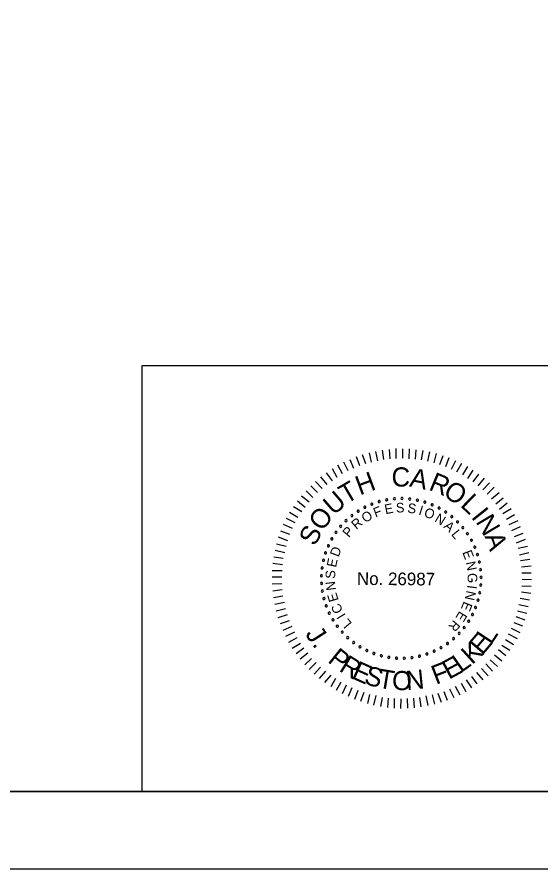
# Model space of a CAD drawing. Extents: x -125.5 to -89.4, y -5.1 to 16.9.
# Drawn here: x -103.71 to -100.32, y -5.07 to 0.43 of the extents above; entities that cross this region are included whole.
import ezdxf

# ---------------------------------------------------------------- set-up
doc = ezdxf.new("R2010")
doc.units = 0
for name, color, linetype in [('BR_BORDER LINES', 7, 'Continuous'), ('BR_TABLE LINES', 7, 'Continuous'), ('BR_TEXT', 7, 'Continuous'), ('Level 31', 7, 'Continuous')]:
    doc.layers.add(name, color=color, linetype=linetype)

msp = doc.modelspace()

# ---------------------------------------------------------------- linework, layer by layer
at = {"layer": 'BR_BORDER LINES'}
for p, q in [((-102.8989, -1.8161), (-97.5337, -1.8161)), ((-102.8989, -4.5661), (-102.8989, -1.8161)), ((-123.6994, -4.5662), (-90.0334, -4.5662))]:
    msp.add_line(p, q, dxfattribs=at)
at = {"layer": 'BR_TABLE LINES'}
msp.add_lwpolyline([(-123.6994, 16.4338), (-90.0334, 16.4338), (-90.0334, -4.5662), (-123.6994, -4.5662)], close=True, dxfattribs=at)
at = {"layer": 'BR_TEXT'}
for p, q in [((-101.3372, -2.423), (-101.3461, -2.362)), ((-101.2977, -2.419), (-101.3015, -2.3581)), ((-101.2582, -2.4168), (-101.2576, -2.3524)), ((-101.2161, -2.4146), (-101.2156, -2.3528)), ((-101.1741, -2.4175), (-101.1718, -2.3531)), ((-101.1338, -2.4204), (-101.129, -2.3595)), ((-101.0952, -2.425), (-101.0844, -2.3642)), ((-101.4937, -2.4629), (-101.5147, -2.4044)), ((-101.4541, -2.4504), (-101.476, -2.3927)), ((-101.418, -2.4404), (-101.4312, -2.3793)), ((-101.3767, -2.4304), (-101.3908, -2.3711)), ((-101.0549, -2.4331), (-101.0407, -2.374)), ((-101.0138, -2.4437), (-100.9979, -2.3829)), ((-100.977, -2.4543), (-100.9551, -2.397)), ((-100.9376, -2.4675), (-100.9157, -2.4093)), ((-101.604, -2.5144), (-101.6344, -2.46)), ((-101.5695, -2.4966), (-101.5957, -2.4406)), ((-101.5325, -2.4798), (-101.556, -2.4238)), ((-100.9017, -2.485), (-100.8738, -2.4294)), ((-100.8658, -2.5024), (-100.8345, -2.4469)), ((-100.8282, -2.5208), (-100.796, -2.467)), ((-101.6704, -2.5593), (-101.7095, -2.5083)), ((-101.6394, -2.5381), (-101.6698, -2.4838)), ((-100.795, -2.5451), (-100.761, -2.4913)), ((-100.7617, -2.5668), (-100.7252, -2.5165)), ((-101.7369, -2.6094), (-101.7786, -2.5644)), ((-101.7041, -2.5847), (-101.744, -2.5346)), ((-100.7293, -2.5928), (-100.6886, -2.5434)), ((-100.6977, -2.618), (-100.6545, -2.5737)), ((-101.7958, -2.6673), (-101.8392, -2.6248)), ((-101.7663, -2.6366), (-101.8106, -2.5925)), ((-100.6697, -2.6456), (-100.6264, -2.6022)), ((-100.6416, -2.6768), (-100.594, -2.6351)), ((-101.8469, -2.732), (-101.8964, -2.6922)), ((-101.8209, -2.6988), (-101.8704, -2.6598)), ((-100.6144, -2.7088), (-100.5677, -2.6705)), ((-101.8686, -2.761), (-101.9224, -2.728)), ((-100.5906, -2.7424), (-100.5414, -2.7033)), ((-100.5686, -2.7718), (-100.516, -2.7396)), ((-101.9104, -2.8319), (-101.9668, -2.804)), ((-101.893, -2.7977), (-101.9467, -2.7656)), ((-100.5466, -2.8089), (-100.4931, -2.7776)), ((-101.9279, -2.8687), (-101.9852, -2.8433)), ((-100.5288, -2.8433), (-100.4711, -2.8164)), ((-100.5111, -2.8804), (-100.4543, -2.856)), ((-101.9454, -2.9072), (-102.0035, -2.8852)), ((-100.4943, -2.9192), (-100.4374, -2.8982)), ((-101.97, -2.9833), (-102.0308, -2.9682)), ((-101.9577, -2.9474), (-102.0193, -2.9246)), ((-100.4809, -2.9596), (-100.4232, -2.9378)), ((-101.9772, -3.0253), (-102.0397, -3.0094)), ((-100.4708, -2.9957), (-100.4107, -2.9816)), ((-100.4626, -3.0378), (-100.4024, -3.0229)), ((-101.9878, -3.0613), (-102.0487, -3.0531)), ((-100.4543, -3.074), (-100.3951, -3.0667)), ((-101.9925, -3.1024), (-102.0542, -3.0951)), ((-100.4478, -3.1152), (-100.3868, -3.1088)), ((-101.9974, -3.183), (-102.06, -3.1825)), ((-101.9954, -3.1419), (-102.0597, -3.1414)), ((-100.4464, -3.1547), (-100.3863, -3.1552)), ((-101.9961, -3.226), (-102.0604, -3.2272)), ((-100.4471, -3.2388), (-100.3871, -3.241)), ((-100.4442, -3.1959), (-100.3833, -3.1964)), ((-101.9938, -3.2646), (-102.0556, -3.2718)), ((-100.4492, -3.2774), (-100.3883, -3.2856)), ((-101.9898, -3.3058), (-102.0509, -3.3148)), ((-101.9799, -3.3454), (-102.0426, -3.3586)), ((-100.4564, -3.3185), (-100.3972, -3.3284)), ((-101.9733, -3.3875), (-102.0344, -3.4016)), ((-100.4742, -3.3999), (-100.4143, -3.415)), ((-100.4653, -3.3579), (-100.4053, -3.3721)), ((-101.9616, -3.4245), (-102.0236, -3.4454)), ((-101.95, -3.4632), (-102.0085, -3.4842)), ((-100.4848, -3.4367), (-100.4275, -3.4586)), ((-101.9331, -3.5003), (-101.9908, -3.5272)), ((-100.5163, -3.512), (-100.4599, -3.5399)), ((-100.4989, -3.4752), (-100.4424, -3.4971)), ((-101.9162, -3.5364), (-101.9731, -3.566)), ((-101.8994, -3.5735), (-101.9537, -3.6048)), ((-100.5346, -3.5479), (-100.4774, -3.5784)), ((-101.8756, -3.6106), (-101.93, -3.6419)), ((-100.5756, -3.6213), (-100.5235, -3.6535)), ((-100.553, -3.5846), (-100.5, -3.6168)), ((-101.8544, -3.6399), (-101.9045, -3.6764)), ((-101.829, -3.6736), (-101.8791, -3.7127)), ((-100.6224, -3.6836), (-100.5764, -3.7234)), ((-100.5981, -3.6503), (-100.5495, -3.6876)), ((-101.8043, -3.7073), (-101.8485, -3.7481)), ((-101.7754, -3.7333), (-101.8204, -3.7784)), ((-100.6502, -3.7168), (-100.6033, -3.7584)), ((-101.7465, -3.7636), (-101.7889, -3.8095)), ((-101.714, -3.7895), (-101.7548, -3.8364)), ((-100.7073, -3.7721), (-100.6648, -3.8188)), ((-100.6787, -3.7423), (-100.6362, -3.7882)), ((-101.6808, -3.8156), (-101.7207, -3.8633)), ((-101.6501, -3.8373), (-101.6814, -3.8894)), ((-100.8057, -3.8443), (-100.7727, -3.8969)), ((-100.772, -3.8231), (-100.7364, -3.8714)), ((-100.7392, -3.7976), (-100.6993, -3.8452)), ((-101.6151, -3.8599), (-101.6464, -3.9137)), ((-101.5809, -3.8799), (-101.608, -3.9355)), ((-101.5442, -3.8974), (-101.5687, -3.953)), ((-100.9135, -3.9026), (-100.8865, -3.9586)), ((-100.8773, -3.8857), (-100.8468, -3.9418)), ((-100.8393, -3.8663), (-100.808, -3.9206)), ((-101.5057, -3.9149), (-101.5276, -3.9713)), ((-101.4663, -3.9272), (-101.4891, -3.9854)), ((-101.4304, -3.9395), (-101.4446, -3.9986)), ((-101.3892, -3.9467), (-101.4044, -4.0084)), ((-101.3499, -3.9582), (-101.3598, -4.0165)), ((-101.0675, -3.9494), (-101.0542, -4.0113)), ((-101.0262, -3.9429), (-101.0112, -4.0022)), ((-100.9892, -3.9311), (-100.9682, -3.9897)), ((-100.9496, -3.9194), (-100.9286, -3.9763)), ((-101.3104, -3.9628), (-101.3152, -4.0246)), ((-101.271, -3.9657), (-101.2715, -4.0275)), ((-101.229, -3.9686), (-101.2295, -4.0296)), ((-101.1869, -3.9664), (-101.1857, -4.0282)), ((-101.1466, -3.9642), (-101.1428, -4.026)), ((-101.1079, -3.9602), (-101.098, -4.0186))]:
    msp.add_line(p, q, dxfattribs=at)
for centre, start, end in [((-101.3681, -2.6945), 16.1422, 196.1422), ((-101.3681, -2.6945), 196.1422, 16.1422), ((-101.3196, -2.6831), 10.6038, 190.6038), ((-101.3196, -2.6831), 190.6038, 10.6038), ((-101.2702, -2.6764), 5.0653, 185.0653), ((-101.2702, -2.6764), 185.0653, 5.0653), ((-101.2204, -2.6745), 359.5268, 179.5268), ((-101.2204, -2.6745), 179.5268, 359.5268), ((-101.1707, -2.6774), 173.9884, 353.9884), ((-101.1707, -2.6774), 353.9884, 173.9884), ((-101.1214, -2.6851), 168.4499, 348.4499), ((-101.1214, -2.6851), 348.4499, 168.4499), ((-101.0732, -2.6976), 342.9114, 162.9114), ((-101.5039, -2.7559), 32.7576, 212.7576), ((-101.4607, -2.7311), 27.2191, 207.2191), ((-101.4607, -2.7311), 207.2191, 27.2191), ((-101.4153, -2.7106), 21.6807, 201.6807), ((-101.4153, -2.7106), 201.6807, 21.6807), ((-101.0732, -2.6976), 162.9114, 342.9114), ((-101.0263, -2.7146), 157.373, 337.373), ((-101.0263, -2.7146), 337.373, 157.373), ((-100.9814, -2.736), 151.8345, 331.8345), ((-100.9814, -2.736), 331.8345, 151.8345), ((-101.5445, -2.7848), 38.2961, 218.2961), ((-101.5445, -2.7848), 218.2961, 38.2961), ((-101.5039, -2.7559), 212.7576, 32.7576), ((-100.9387, -2.7617), 146.2961, 326.2961), ((-100.9387, -2.7617), 326.2961, 146.2961), ((-100.8987, -2.7914), 140.7576, 320.7576), ((-100.8987, -2.7914), 320.7576, 140.7576), ((-101.6164, -2.8536), 49.373, 229.373), ((-101.6164, -2.8536), 229.373, 49.373), ((-101.5821, -2.8175), 43.8345, 223.8345), ((-101.5821, -2.8175), 223.8345, 43.8345), ((-100.8617, -2.8249), 135.2191, 315.2191), ((-100.8617, -2.8249), 315.2191, 135.2191), ((-100.8282, -2.8617), 129.6807, 309.6807), ((-100.8282, -2.8617), 309.6807, 129.6807), ((-101.6471, -2.8929), 54.9114, 234.9114), ((-101.6471, -2.8929), 234.9114, 54.9114), ((-100.7983, -2.9016), 124.1422, 304.1422), ((-100.7983, -2.9016), 304.1422, 124.1422), ((-101.6738, -2.935), 60.4499, 240.4499), ((-101.6738, -2.935), 240.4499, 60.4499), ((-100.7724, -2.9442), 118.6038, 298.6038), ((-100.7724, -2.9442), 298.6038, 118.6038), ((-101.7145, -3.0258), 71.5268, 251.5268), ((-101.7145, -3.0258), 251.5268, 71.5268), ((-101.6964, -2.9794), 65.9884, 245.9884), ((-101.6964, -2.9794), 245.9884, 65.9884), ((-100.7508, -2.9891), 113.0653, 293.0653), ((-100.7508, -2.9891), 293.0653, 113.0653), ((-101.7281, -3.0738), 77.0653, 257.0653), ((-101.7281, -3.0738), 257.0653, 77.0653), ((-100.7336, -3.0359), 107.5268, 287.5268), ((-100.7336, -3.0359), 287.5268, 107.5268), ((-100.721, -3.0841), 101.9884, 281.9884), ((-100.721, -3.0841), 281.9884, 101.9884), ((-101.737, -3.1228), 82.6038, 262.6038), ((-101.737, -3.1228), 262.6038, 82.6038), ((-100.7131, -3.1333), 96.4499, 276.4499), ((-100.7131, -3.1333), 276.4499, 96.4499), ((-101.7411, -3.1724), 88.1422, 268.1422), ((-101.7411, -3.1724), 268.1422, 88.1422), ((-100.71, -3.183), 90.9114, 270.9114), ((-100.71, -3.183), 270.9114, 90.9114), ((-101.7404, -3.2223), 93.6807, 273.6807), ((-101.7404, -3.2223), 273.6807, 93.6807), ((-100.7118, -3.2328), 85.373, 265.373), ((-100.7118, -3.2328), 265.373, 85.373), ((-101.7349, -3.2718), 99.2191, 279.2191), ((-101.7349, -3.2718), 279.2191, 99.2191), ((-100.7183, -3.2822), 79.8345, 259.8345), ((-100.7183, -3.2822), 259.8345, 79.8345), ((-101.7246, -3.3206), 104.7576, 284.7576), ((-101.7246, -3.3206), 284.7576, 104.7576), ((-100.7295, -3.3308), 74.2961, 254.2961), ((-100.7295, -3.3308), 254.2961, 74.2961), ((-101.7097, -3.3681), 110.2961, 290.2961), ((-101.7097, -3.3681), 290.2961, 110.2961), ((-101.6903, -3.414), 115.8345, 295.8345), ((-101.6903, -3.414), 295.8345, 115.8345), ((-100.7454, -3.378), 68.7576, 248.7576), ((-100.7454, -3.378), 248.7576, 68.7576), ((-101.6665, -3.4578), 121.373, 301.373), ((-101.6665, -3.4578), 301.373, 121.373), ((-100.7904, -3.4668), 57.6807, 237.6807), ((-100.7904, -3.4668), 237.6807, 57.6807), ((-100.7658, -3.4235), 63.2191, 243.2191), ((-100.7658, -3.4235), 243.2191, 63.2191), ((-101.6386, -3.4991), 126.9114, 306.9114), ((-101.6386, -3.4991), 306.9114, 126.9114), ((-100.8192, -3.5075), 52.1422, 232.1422), ((-100.8192, -3.5075), 232.1422, 52.1422), ((-101.6069, -3.5375), 132.4499, 312.4499), ((-101.6069, -3.5375), 312.4499, 132.4499), ((-101.5716, -3.5727), 137.9884, 317.9884), ((-101.5716, -3.5727), 317.9884, 137.9884), ((-100.8877, -3.5797), 41.0653, 221.0653), ((-100.8517, -3.5452), 46.6038, 226.6038), ((-100.8517, -3.5452), 226.6038, 46.6038), ((-101.5331, -3.6043), 143.5268, 323.5268), ((-101.5331, -3.6043), 323.5268, 143.5268), ((-101.4917, -3.632), 149.0653, 329.0653), ((-101.4917, -3.632), 329.0653, 149.0653), ((-100.9269, -3.6105), 35.5268, 215.5268), ((-100.9269, -3.6105), 215.5268, 35.5268), ((-100.8877, -3.5797), 221.0653, 41.0653), ((-101.4478, -3.6556), 154.6038, 334.6038), ((-101.4478, -3.6556), 334.6038, 154.6038), ((-101.4018, -3.6749), 160.1422, 340.1422), ((-101.4018, -3.6749), 340.1422, 160.1422), ((-101.3542, -3.6896), 345.6807, 165.6807), ((-101.0595, -3.6784), 18.9114, 198.9114), ((-101.0595, -3.6784), 198.9114, 18.9114), ((-101.0132, -3.6601), 24.4499, 204.4499), ((-101.0132, -3.6601), 204.4499, 24.4499), ((-100.9688, -3.6374), 29.9884, 209.9884), ((-100.9688, -3.6374), 209.9884, 29.9884), ((-101.3542, -3.6896), 165.6807, 345.6807), ((-101.3054, -3.6997), 351.2191, 171.2191), ((-101.3054, -3.6997), 171.2191, 351.2191), ((-101.2559, -3.705), 356.7576, 176.7576), ((-101.2559, -3.705), 176.7576, 356.7576), ((-101.2061, -3.7055), 2.2961, 182.2961), ((-101.2061, -3.7055), 182.2961, 2.2961), ((-101.1564, -3.7012), 7.8345, 187.8345), ((-101.1564, -3.7012), 187.8345, 7.8345), ((-101.1074, -3.6921), 13.373, 193.373), ((-101.1074, -3.6921), 193.373, 13.373)]:
    msp.add_arc(centre, 0.00701, start, end, dxfattribs=at)
at = {"layer": 'Level 31'}
msp.add_lwpolyline([(-125.5328, -5.0661), (-89.5328, -5.0661), (-89.5328, 16.9339), (-125.5328, 16.9339)], close=True, dxfattribs=at)

# ---------------------------------------------------------------- texts
at = {"layer": 'BR_TEXT'}
for s, height, rotation, p in [('C', 0.1241, 359.5482, (-101.2889, -2.5969)), ('H', 0.1241, 20.3637, (-101.4933, -2.6552)), ('A', 0.1241, 348.1981, (-101.1775, -2.5961)), ('R', 0.1241, 337.4344, (-101.0542, -2.616)), ('T', 0.1241, 30.4992, (-101.5812, -2.7128)), ('O', 0.1239, 326.5869, (-100.962, -2.6528)), ('U', 0.1241, 40.8022, (-101.6624, -2.7875)), ('L', 0.1241, 315.9488, (-100.8494, -2.7205)), ('O', 0.1241, 52.0267, (-101.7369, -2.8914)), ('F', 0.0622, 20.6127, (-101.392, -2.7981)), ('E', 0.0622, 11.4103, (-101.3269, -2.7764)), ('S', 0.0622, 2.208, (-101.2591, -2.7654)), ('S', 0.0622, 352.6608, (-101.1878, -2.7657)), ('I', 0.0622, 343.1136, (-101.1175, -2.7777)), ('O', 0.0622, 338.4392, (-101.0841, -2.7878)), ('I', 0.1241, 308.6613, (-100.778, -2.7948)), ('R', 0.0622, 40.3949, (-101.5156, -2.878)), ('O', 0.0622, 30.8477, (-101.4594, -2.8341)), ('N', 0.0622, 328.2042, (-101.0145, -2.8192)), ('N', 0.1241, 300.7037, (-100.7474, -2.8242)), ('S', 0.1239, 63.2511, (-101.7823, -2.9871)), ('P', 0.0622, 49.9421, (-101.5636, -2.9306)), ('A', 0.0622, 318.657, (-100.9555, -2.8592)), ('L', 0.0622, 309.4546, (-100.9057, -2.9066)), ('A', 0.1241, 289.4792, (-100.6882, -2.9172)), ('D', 0.0622, 69.0364, (-101.6306, -3.0559)), ('E', 0.0622, 291.049, (-100.8319, -3.0219)), ('E', 0.0622, 78.2388, (-101.6472, -3.1226)), ('N', 0.0622, 281.8466, (-100.8097, -3.0869)), ('S', 0.0622, 87.786, (-101.6529, -3.1936)), ('No. 26987', 0.08175, 359.5268, (-101.5118, -3.232)), ('G', 0.0622, 272.2995, (-100.7979, -3.1572)), ('N', 0.0622, 97.3332, (-101.6467, -3.2646)), ('I', 0.0622, 262.4084, (-100.7983, -3.231)), ('E', 0.0622, 106.5355, (-101.6297, -3.3312)), ('N', 0.0622, 257.7339, (-100.8028, -3.2656)), ('C', 0.0622, 116.4266, (-101.5998, -3.3987)), ('E', 0.0622, 248.1867, (-100.8209, -3.3346)), ('E', 0.0622, 238.9844, (-100.8488, -3.3973)), ('I', 0.0622, 121.1011, (-101.5818, -3.4285)), ('L', 0.0622, 129.9595, (-101.5411, -3.4807)), ('R', 0.0622, 229.782, (-100.8865, -3.4548)), ('J', 0.1236, 302.9559, (-101.849, -3.5492)), ('E', 0.1236, 49.3639, (-100.703, -3.6911)), ('L', 0.1236, 56.4247, (-100.6455, -3.6233)), ('.', 0.1236, 309.3974, (-101.8049, -3.6172)), ('K', 0.1236, 42.3031, (-100.7683, -3.7512)), ('P', 0.1236, 321.1035, (-101.7065, -3.7264)), ('R', 0.1236, 328.5359, (-101.6332, -3.7844)), ('E', 0.1236, 335.9684, (-101.5531, -3.8325)), ('F', 0.1236, 21.1206, (-101.0013, -3.8776)), ('E', 0.1236, 28.1814, (-100.9186, -3.8452)), ('L', 0.1236, 35.2422, (-100.8406, -3.8028)), ('S', 0.1236, 343.0292, (-101.4718, -3.8682)), ('T', 0.1236, 350.4617, (-101.3821, -3.8947)), ('O', 0.1236, 358.1419, (-101.2867, -3.9097)), ('N', 0.1236, 5.8221, (-101.1902, -3.9118))]:
    msp.add_text(s, height=height, rotation=rotation, dxfattribs=at).set_placement(p)

doc.saveas('drawing.dxf')
